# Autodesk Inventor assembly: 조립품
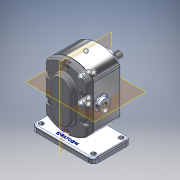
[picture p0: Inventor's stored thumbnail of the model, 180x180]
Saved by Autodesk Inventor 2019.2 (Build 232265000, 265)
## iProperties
Created: 2019-03
Part Number: 조립품
Material: 일반
Document SubType Name: Assembly
Designer: User
Author: User
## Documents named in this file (11)
- C:\Users\User\Desktop\490307V1028\조립품.iam
- C:\Users\User\Desktop\490307V1028\본체.ipt
- C:\Users\User\Desktop\490307V1028\메인축.ipt
- C:\Users\User\Desktop\490307V1028\키 6 x 6 x 18.ipt
- C:\Users\User\Desktop\490307V1028\스퍼기어.ipt
- C:\Users\User\Desktop\490307V1028\베어링부시.ipt
- C:\Users\User\Desktop\490307V1028\서브축.ipt
- C:\Users\User\Desktop\490307V1028\개스킷.ipt
- C:\Users\User\Desktop\490307V1028\커버.ipt
- C:\Users\User\Desktop\490307V1028\볼트 M5.ipt
- C:\Users\User\Desktop\490307V1028\오일 실 16 28 7.ipt
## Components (1 placed, 1 different names)
1. 개스킷:1
